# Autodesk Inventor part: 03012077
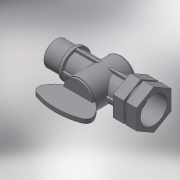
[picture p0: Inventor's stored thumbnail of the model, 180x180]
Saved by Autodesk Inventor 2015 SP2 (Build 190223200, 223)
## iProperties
Created: 2017-05
Part Number: 03012077
Material: Generic
Description: PLASSON 1/4 TURN VALVE MALE THREADED X FEMALE THREADED 3/4"X3/4"
Document SubType Name: Modeling
Designer: KIM
Density: 1 g/cm^3
Appearance: Default
Author: KIM
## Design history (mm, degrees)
derived "03012.ipt"
feature "Solid1::03012.ipt"
tag "TaggingFeature1"
body "Solid1"
other parameters: "d0" = 97, "d1" = 17, "d3" = 24.117, "d4" = 12.59228, "d15" = 24.117, "d16" = 28.9404, "d17" = 20.4, "d19" = 0.245, "d31" = 49, "d32" = 0, "d33" = 19.6, "d34" = 24.5, "d36" = 15.68, "d38" = 2.45, "d45" = 49, "d46" = 52, "d47" = 45, "d48" = 4, "d49" = 0, "d50" = 29, "d51" = 2, "d52" = 0, "d63" = 26.441, "d64" = 34, "d66" = 18, "d67" = 23.4, "d68" = 31.7292, "d70" = 10.5646, "d71" = 0, "d72" = 10.5646, "d73" = 0, "d74" = 8.81367, "d75" = 2.6441, "d76" = 0, "d78" = 360 deg, "H_" = 97, "A_" = 49, "l_3" = 18, "l_2" = 17, "R_" = 24.117, "Rp_" = 26.441, "d69" = 10.5646
